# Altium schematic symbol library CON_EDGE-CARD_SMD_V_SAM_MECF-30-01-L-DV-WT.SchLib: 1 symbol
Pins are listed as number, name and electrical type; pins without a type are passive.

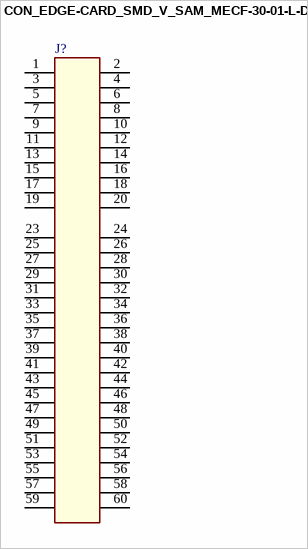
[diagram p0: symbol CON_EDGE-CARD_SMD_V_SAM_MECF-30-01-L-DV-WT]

## CON_EDGE-CARD_SMD_V_SAM_MECF-30-01-L-DV-WT
designator J?
pins: 1, 2, 3, 4, 5, 6, 7, 8, 9, 10, 11, 12, 13, 14, 15, 16, 17, 18, 19, 20, 23, 24, 25, 26, 27, 28, 29, 30, 31, 32, 33, 34, 35, 36, 37, 38, 39, 40, 41, 42, 43, 44, 45, 46, 47, 48, 49, 50, 51, 52, 53, 54, 55, 56, 57, 58, 59, 60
